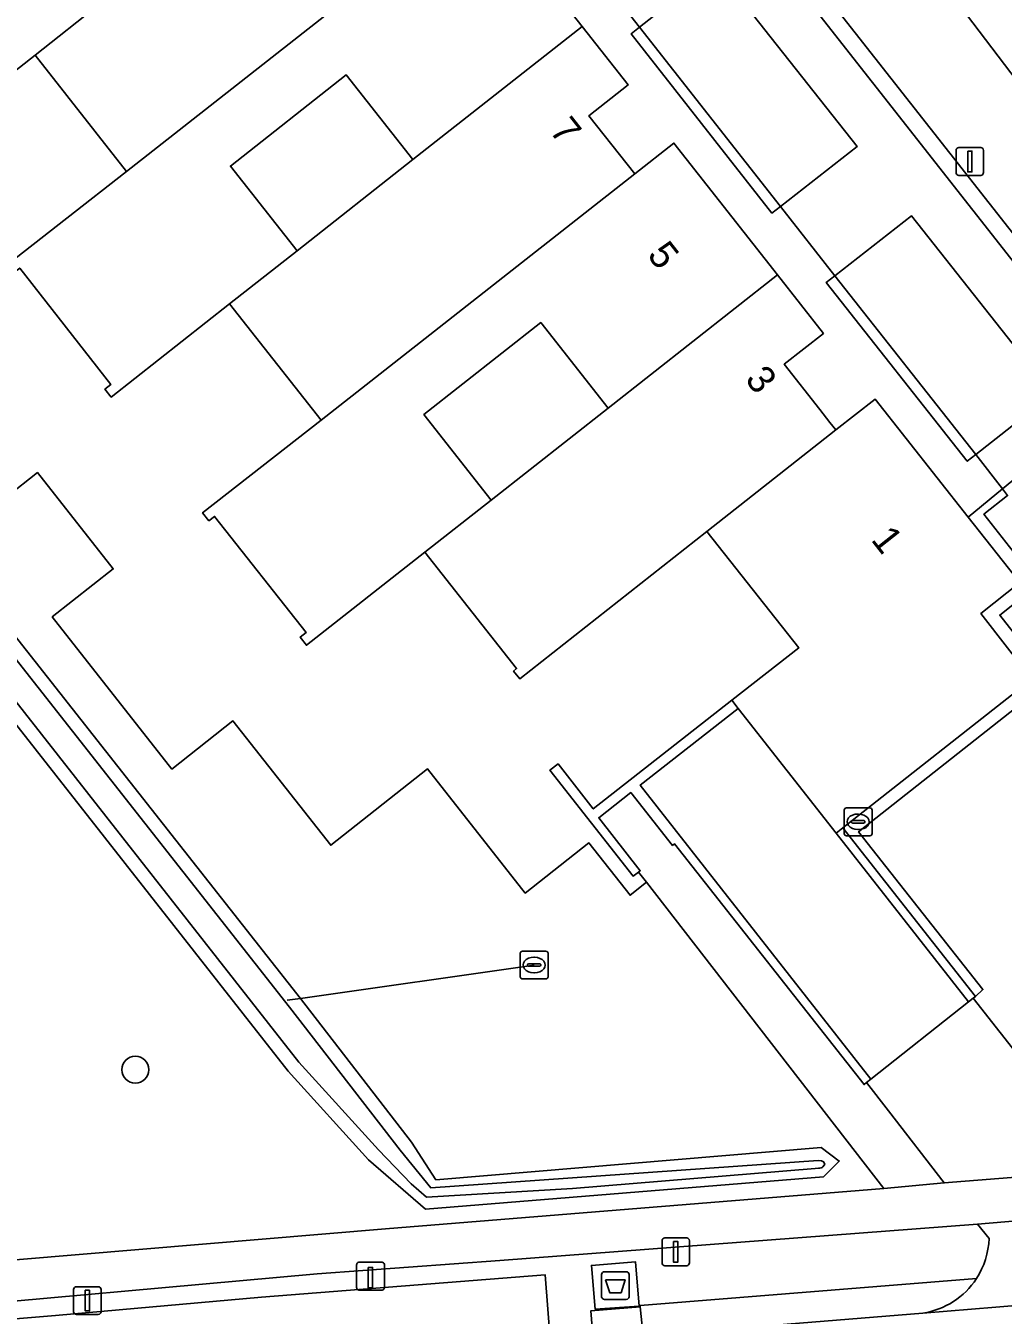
# Model space of a CAD drawing. Extents: x 156661 to 157576, y 383570 to 384425.
# Drawn here: x 157036.77 to 157072.04, y 383934.25 to 383980.76 of the extents above; entities that cross this region are included whole.
import ezdxf

# ---------------------------------------------------------------- set-up
doc = ezdxf.new("R2010")
doc.units = 0
for name, color, linetype in [('IMGEO_Afval_apart_plaats', 7, 'Continuous'), ('IMGEO_Berm_groen', 7, 'Continuous'), ('IMGEO_Boom', 7, 'Continuous'), ('IMGEO_Brandkraan', 7, 'Continuous'), ('IMGEO_Duiker', 7, 'Continuous'), ('IMGEO_Erf', 7, 'Continuous'), ('IMGEO_Fietspad_gesloten', 7, 'Continuous'), ('IMGEO_Groenvoorziening', 7, 'Continuous'), ('IMGEO_Laadpaal', 7, 'Continuous'), ('IMGEO_Lichtmast', 7, 'Continuous'), ('IMGEO_Muur', 7, 'Continuous'), ('IMGEO_Oever', 7, 'Continuous'), ('IMGEO_Pand', 7, 'Continuous'), ('IMGEO_Pand_nummerreeks', 7, 'Continuous'), ('IMGEO_Parkeervlak_open', 7, 'Continuous'), ('IMGEO_Rijbaan_lokaal_gesloten', 7, 'Continuous'), ('IMGEO_Rijbaan_lokaal_open', 7, 'Continuous'), ('IMGEO_Rioolput', 7, 'Continuous'), ('IMGEO_Voetpad_gesloten', 7, 'Continuous'), ('IMGEO_Voetpad_open', 7, 'Continuous'), ('IMGEO_Waterloop', 7, 'Continuous')]:
    doc.layers.add(name, color=color, linetype=linetype)

msp = doc.modelspace()

# ---------------------------------------------------------------- linework, layer by layer
at = {"layer": 'IMGEO_Afval_apart_plaats'}
for p, q in [((157057.55, 383934.917), (157057.55, 383935.717)), ((157057.55, 383935.717), (157057.55, 383934.917)), ((157057.65, 383935.817), (157058.44, 383935.817)), ((157058.44, 383935.817), (157057.65, 383935.817)), ((157058.54, 383935.717), (157058.54, 383934.917)), ((157058.54, 383934.917), (157058.54, 383935.717)), ((157058.44, 383934.817), (157057.65, 383934.817)), ((157057.65, 383934.817), (157058.44, 383934.817))]:
    msp.add_line(p, q, dxfattribs=at)
msp.add_lwpolyline([(157057.693, 383935.531), (157058.397, 383935.531), (157058.248, 383935.061), (157057.842, 383935.061), (157057.693, 383935.531)], dxfattribs=at)
for centre, start, end in [((157057.65, 383935.717), 90, 180), ((157057.65, 383935.717), 90, 180), ((157058.44, 383935.717), 0, 90), ((157058.44, 383935.717), 360, 90), ((157057.65, 383934.917), 180, 270), ((157057.65, 383934.917), 180, 270), ((157058.44, 383934.917), 270, 0), ((157058.44, 383934.917), 270, 0)]:
    msp.add_arc(centre, 0.1, start, end, dxfattribs=at)
at = {"layer": 'IMGEO_Berm_groen'}
for points in [[(157063.404, 383990.789), (157060.448, 383988.467), (157093.57, 383946.344), (157095.404, 383947.68)], [(157089.259, 383956.768), (157063.404, 383990.789)], [(157071.526, 383937.018), (157071.115, 383937.537), (157053.882, 383936.219), (157047.285, 383935.737), (157032.066, 383934.37), (156967.792, 383928.413), (156970.285, 383925.601), (156970.036, 383928.144), (156971.344, 383928.273), (156979.881, 383929.112), (156997.191, 383930.813), (157022.212, 383932.944), (157037.851, 383934.234), (157045.273, 383934.895), (157055.512, 383935.702), (157055.71, 383933.229), (157057.249, 383933.355), (157057.154, 383934.404), (157058.945, 383934.553), (157058.941, 383934.597), (157071.071, 383935.569)]]:
    msp.add_lwpolyline(points, dxfattribs=at)
msp.add_lwpolyline([(157058.904, 383934.58), (157057.318, 383934.466), (157057.183, 383936.043), (157058.771, 383936.176)], close=True, dxfattribs=at)
msp.add_arc((157068.713, 383937.106), 2.815, 326.9161, 358.2183, dxfattribs=at)
at = {"layer": 'IMGEO_Boom'}
msp.add_circle((157040.724, 383943.105), 0.489, dxfattribs=at)
at = {"layer": 'IMGEO_Brandkraan'}
for p, q in [((157066.304, 383951.619), (157066.304, 383952.471)), ((157066.379, 383952.545), (157067.231, 383952.545)), ((157066.792, 383952.325), (157066.817, 383952.325)), ((157067.305, 383952.471), (157067.305, 383951.619)), ((157066.563, 383952.039), (157066.563, 383952.051)), ((157067.001, 383952.002), (157066.603, 383952.002)), ((157066.606, 383952.088), (157067.004, 383952.088)), ((157067.047, 383952.051), (157067.047, 383952.039)), ((157067.231, 383951.545), (157066.379, 383951.545)), ((157066.815, 383951.765), (157066.79, 383951.765))]:
    msp.add_line(p, q, dxfattribs=at)
for points in [[(157066.304, 383951.619), (157066.304, 383952.471)], [(157066.379, 383952.545), (157067.231, 383952.545)], [(157067.305, 383952.471), (157067.305, 383951.619)], [(157067.231, 383951.545), (157066.379, 383951.545)]]:
    msp.add_lwpolyline(points, dxfattribs=at)
for centre, radius, start, end in [((157066.381, 383952.469), 0.0765, 91.552, 178.448), ((157066.381, 383952.469), 0.0765, 91.552, 178.448), ((157067.229, 383952.469), 0.0765, 1.552, 88.448), ((157067.229, 383952.469), 0.0765, 1.552, 88.448), ((157066.603, 383952.048), 0.0403, 85.8775, 175.7526), ((157066.6, 383952.038), 0.0366, 178.938, 274.7102), ((157067.004, 383952.045), 0.043, 264.8664, 352.4533), ((157067.008, 383952.05), 0.0386, 1.7309, 96.639), ((157066.381, 383951.621), 0.0765, 181.552, 268.448), ((157066.381, 383951.621), 0.0765, 181.552, 268.448), ((157067.229, 383951.621), 0.0765, 271.552, 358.448), ((157067.229, 383951.621), 0.0765, 271.552, 358.448)]:
    msp.add_arc(centre, radius, start, end, dxfattribs=at)
for centre, major_axis, ratio, start_param, end_param in [((157066.791, 383952.045), (-0.387, 0.002), 0.722429, 4.712389, 7.853982), ((157066.816, 383952.045), (-0.39, 0.002), 0.717154, 1.570796, 4.712389)]:
    msp.add_ellipse(centre, major_axis=major_axis, ratio=ratio, start_param=start_param, end_param=end_param, dxfattribs=at)
at = {"layer": 'IMGEO_Duiker'}
msp.add_lwpolyline([(157046.201, 383945.607), (157046.683, 383945.676), (157055.116, 383946.879)], dxfattribs=at)
at = {"layer": 'IMGEO_Erf'}
for points in [[(157053.11, 383985.486), (157056.845, 383980.735), (157058.505, 383978.625), (157057.09, 383977.512), (157058.743, 383975.415), (157060.159, 383976.527), (157063.891, 383971.776), (157065.55, 383969.664), (157064.135, 383968.552), (157065.422, 383966.915), (157065.787, 383966.451), (157065.999, 383966.182), (157067.413, 383967.295), (157070.773, 383963.032), (157072.009, 383964.052), (157071.046, 383965.29), (157070.739, 383965.049), (157065.654, 383971.5), (157065.96, 383971.742), (157064.001, 383974.244), (157063.694, 383974.003), (157058.612, 383980.465), (157058.919, 383980.706), (157056.954, 383983.211)], [(157036.106, 383972.141), (157040.402, 383975.505), (157037.106, 383979.7), (157032.805, 383976.321)], [(157034.995, 383962.908), (157037.195, 383964.64), (157039.929, 383961.167), (157037.729, 383959.435), (157042.046, 383953.95), (157044.246, 383955.682), (157047.773, 383951.203), (157051.268, 383953.956), (157054.795, 383949.476), (157057.089, 383951.283), (157058.574, 383949.397), (157059.17, 383949.866), (157058.881, 383950.231), (157058.684, 383950.086), (157055.684, 383953.903), (157055.975, 383954.132), (157057.249, 383952.511), (157062.248, 383956.428), (157064.661, 383958.319), (157061.345, 383962.52), (157054.596, 383957.207), (157054.37, 383957.482), (157054.482, 383957.573), (157051.171, 383961.766), (157046.901, 383958.415), (157046.673, 383958.706), (157046.885, 383958.873), (157043.583, 383963.061), (157043.378, 383962.902), (157043.151, 383963.194), (157047.431, 383966.531), (157044.124, 383970.724), (157039.859, 383967.365), (157039.63, 383967.648), (157039.84, 383967.818), (157036.555, 383972.018)]]:
    msp.add_lwpolyline(points, dxfattribs=at)
for points in [[(157046.559, 383972.64), (157050.739, 383975.93), (157048.336, 383978.984), (157044.156, 383975.694)], [(157053.565, 383963.65), (157057.781, 383966.968), (157055.353, 383970.054), (157051.137, 383966.736)]]:
    msp.add_lwpolyline(points, close=True, dxfattribs=at)
at = {"layer": 'IMGEO_Fietspad_gesloten'}
msp.add_lwpolyline([(156992.1, 384084.489), (156997.679, 384077.272), (157008.067, 384063.603), (157009.29, 384061.994), (157062.312, 383992.226), (157063.404, 383990.789), (157089.259, 383956.768)], dxfattribs=at)
at = {"layer": 'IMGEO_Groenvoorziening'}
for points in [[(157046.683, 383945.676), (157050.688, 383940.493), (157051.572, 383939.133), (157065.473, 383940.297), (157066.12, 383939.807), (157065.553, 383939.239), (157051.199, 383938.08), (157049.143, 383939.851), (157046.243, 383943.057), (156999.575, 384002.48), (156979.971, 384027.441), (156979.057, 384027.27), (156978.106, 384028.607), (156978.828, 384029.096), (156976.159, 384036.79), (156976.265, 384037.915)], [(156977.044, 384038.227), (156977.796, 384037.236), (156980.256, 384030.02), (157001.17, 384003.466), (157046.683, 383945.676)], [(157074.729, 383966.297), (157072.009, 383964.052), (157072.196, 383963.812), (157071.339, 383963.137), (157073.325, 383960.616), (157071.911, 383959.501), (157073.761, 383957.153), (157066.822, 383951.69), (157071.306, 383945.993), (157071.042, 383945.746), (157070.957, 383945.682), (157075.823, 383939.488), (157083.24, 383940.16)], [(157027.632, 383935.51), (157049.754, 383937.359), (157067.736, 383938.825), (157059.17, 383949.866), (157058.574, 383949.397), (157057.089, 383951.283), (157054.795, 383949.476), (157051.268, 383953.956), (157047.773, 383951.203), (157044.246, 383955.682), (157042.046, 383953.95), (157037.729, 383959.435), (157039.929, 383961.167), (157037.195, 383964.64), (157034.995, 383962.908)]]:
    msp.add_lwpolyline(points, dxfattribs=at)
for points in [[(157061.655, 383982.874), (157058.919, 383980.706), (157064.001, 383974.244), (157066.772, 383976.407)], [(157068.728, 383973.903), (157065.96, 383971.742), (157071.046, 383965.29), (157073.818, 383967.471)]]:
    msp.add_lwpolyline(points, close=True, dxfattribs=at)
at = {"layer": 'IMGEO_Laadpaal'}
for p, q in [((157048.711, 383936.074), (157048.711, 383935.233)), ((157048.711, 383936.074), (157048.711, 383935.233)), ((157049.627, 383936.158), (157048.786, 383936.158)), ((157049.627, 383936.158), (157048.786, 383936.158)), ((157049.711, 383935.242), (157049.711, 383936.083)), ((157049.711, 383935.242), (157049.711, 383936.083)), ((157048.795, 383935.158), (157049.636, 383935.158)), ((157048.795, 383935.158), (157049.636, 383935.158))]:
    msp.add_line(p, q, dxfattribs=at)
msp.add_lwpolyline([(157049.126, 383935.971), (157049.286, 383935.971), (157049.286, 383935.238), (157049.126, 383935.238), (157049.126, 383935.971)], dxfattribs=at)
for centre, start, end in [((157048.789, 383936.08), 92.4484, 184.2845), ((157048.789, 383936.08), 92.4484, 184.2845), ((157049.633, 383936.08), 2.4484, 94.2845), ((157049.633, 383936.08), 2.4484, 94.2845), ((157048.789, 383935.236), 182.4484, 274.2845), ((157048.789, 383935.236), 182.4484, 274.2845), ((157049.633, 383935.236), 272.4484, 4.2845), ((157049.633, 383935.236), 272.4484, 4.2845)]:
    msp.add_arc(centre, 0.0779, start, end, dxfattribs=at)
at = {"layer": 'IMGEO_Lichtmast'}
for p, q in [((157070.336, 383975.463), (157070.336, 383976.263)), ((157070.336, 383976.263), (157070.336, 383975.463)), ((157070.436, 383976.363), (157071.226, 383976.363)), ((157071.226, 383976.363), (157070.436, 383976.363)), ((157071.326, 383976.263), (157071.326, 383975.463)), ((157071.326, 383975.463), (157071.326, 383976.263)), ((157071.226, 383975.363), (157070.436, 383975.363)), ((157070.436, 383975.363), (157071.226, 383975.363)), ((157059.828, 383937.036), (157060.618, 383937.036)), ((157060.618, 383937.036), (157059.828, 383937.036)), ((157059.728, 383936.136), (157059.728, 383936.936)), ((157059.728, 383936.936), (157059.728, 383936.136)), ((157060.718, 383936.936), (157060.718, 383936.136)), ((157060.718, 383936.136), (157060.718, 383936.936)), ((157060.618, 383936.036), (157059.828, 383936.036)), ((157059.828, 383936.036), (157060.618, 383936.036)), ((157038.5, 383934.377), (157038.5, 383935.177)), ((157038.5, 383935.177), (157038.5, 383934.377)), ((157038.6, 383935.277), (157039.39, 383935.277)), ((157039.39, 383935.277), (157038.6, 383935.277)), ((157039.49, 383935.177), (157039.49, 383934.377)), ((157039.49, 383934.377), (157039.49, 383935.177)), ((157039.39, 383934.277), (157038.6, 383934.277)), ((157038.6, 383934.277), (157039.39, 383934.277))]:
    msp.add_line(p, q, dxfattribs=at)
for points in [[(157070.756, 383976.238), (157070.906, 383976.238), (157070.906, 383975.488), (157070.756, 383975.488), (157070.756, 383976.238)], [(157060.148, 383936.911), (157060.298, 383936.911), (157060.298, 383936.161), (157060.148, 383936.161), (157060.148, 383936.911)], [(157038.92, 383935.152), (157039.07, 383935.152), (157039.07, 383934.402), (157038.92, 383934.402), (157038.92, 383935.152)]]:
    msp.add_lwpolyline(points, dxfattribs=at)
for centre, start, end in [((157070.436, 383976.263), 90, 180), ((157070.436, 383976.263), 90, 180), ((157071.226, 383976.263), 0, 90), ((157071.226, 383976.263), 360, 90), ((157070.436, 383975.463), 180, 270), ((157070.436, 383975.463), 180, 270), ((157071.226, 383975.463), 270, 0), ((157071.226, 383975.463), 270, 0), ((157059.828, 383936.936), 90, 180), ((157059.828, 383936.936), 90, 180), ((157060.618, 383936.936), 0, 90), ((157060.618, 383936.936), 360, 90), ((157059.828, 383936.136), 180, 270), ((157059.828, 383936.136), 180, 270), ((157060.618, 383936.136), 270, 0), ((157060.618, 383936.136), 270, 0), ((157038.6, 383935.177), 90, 180), ((157038.6, 383935.177), 90, 180), ((157039.39, 383935.177), 0, 90), ((157039.39, 383935.177), 360, 90), ((157038.6, 383934.377), 180, 270), ((157038.6, 383934.377), 180, 270), ((157039.39, 383934.377), 270, 0), ((157039.39, 383934.377), 270, 0)]:
    msp.add_arc(centre, 0.1, start, end, dxfattribs=at)
at = {"layer": 'IMGEO_Muur'}
for points in [[(157058.919, 383980.706), (157058.612, 383980.465), (157063.694, 383974.003), (157064.001, 383974.244)], [(157065.96, 383971.742), (157065.654, 383971.5), (157070.739, 383965.049), (157071.046, 383965.29)], [(157071.042, 383945.746), (157071.306, 383945.993), (157066.822, 383951.69), (157073.761, 383957.153), (157071.911, 383959.501), (157073.325, 383960.616), (157071.339, 383963.137), (157072.196, 383963.812), (157072.009, 383964.052), (157070.773, 383963.032), (157072.633, 383960.672), (157071.232, 383959.559), (157073.067, 383957.196), (157066.256, 383951.828)], [(157057.249, 383952.511), (157055.975, 383954.132), (157055.684, 383953.903), (157058.684, 383950.086), (157058.881, 383950.231), (157058.942, 383950.278), (157057.444, 383952.194), (157058.602, 383953.1), (157060.106, 383951.194), (157060.178, 383951.252), (157067.017, 383942.57), (157067.104, 383942.64), (157067.264, 383942.768), (157058.943, 383953.37), (157062.475, 383956.138), (157062.248, 383956.428)], [(157071.042, 383945.746), (157066.256, 383951.828), (157066.015, 383951.639), (157070.785, 383945.551), (157070.957, 383945.682)]]:
    msp.add_lwpolyline(points, close=True, dxfattribs=at)
at = {"layer": 'IMGEO_Oever'}
for points in [[(156976.265, 384037.915), (156976.159, 384036.79), (156978.828, 384029.096), (156978.106, 384028.607), (156979.057, 384027.27), (156979.971, 384027.441), (156999.575, 384002.48), (157046.243, 383943.057), (157049.143, 383939.851), (157051.199, 383938.08), (157065.553, 383939.239), (157066.12, 383939.807), (157065.473, 383940.297), (157051.572, 383939.133), (157050.688, 383940.493), (157046.683, 383945.676), (157001.17, 384003.466), (156980.256, 384030.02)], [(157029.374, 383966.839), (157046.286, 383945.366), (157050.277, 383940.201), (157051.383, 383938.849), (157065.364, 383939.825), (157065.479, 383939.817), (157065.509, 383939.807), (157065.555, 383939.782), (157065.595, 383939.726), (157065.597, 383939.703), (157065.582, 383939.657), (157065.534, 383939.6), (157065.511, 383939.583), (157065.468, 383939.563), (157065.421, 383939.553), (157065.372, 383939.55), (157065.257, 383939.543), (157056.494, 383938.823), (157051.23, 383938.505), (157050.675, 383938.988), (157049.496, 383940.212), (157046.629, 383943.382), (157028.661, 383966.26)]]:
    msp.add_lwpolyline(points, dxfattribs=at)
at = {"layer": 'IMGEO_Pand'}
for points in [[(157043.672, 383984.868), (157049.803, 383989.693), (157046.041, 383994.477), (157044.634, 383993.37), (157033.325, 383984.498), (157029.036, 383981.139), (157029.261, 383980.846), (157029.468, 383981.005), (157032.788, 383976.809), (157032.568, 383976.652), (157032.805, 383976.321), (157037.106, 383979.7), (157039.483, 383981.571), (157037.01, 383984.714), (157041.198, 383988.011)], [(157051.695, 383984.374), (157050.049, 383986.469), (157051.464, 383987.581), (157049.803, 383989.693), (157043.672, 383984.868), (157039.483, 383981.571), (157037.106, 383979.7), (157040.402, 383975.505)], [(157050.739, 383975.93), (157056.845, 383980.735), (157053.11, 383985.486), (157051.695, 383984.374), (157040.402, 383975.505), (157036.106, 383972.141), (157036.331, 383971.847), (157036.555, 383972.018), (157039.84, 383967.818), (157039.63, 383967.648), (157039.859, 383967.365), (157044.124, 383970.724), (157046.559, 383972.64), (157044.156, 383975.694), (157048.336, 383978.984)], [(157058.743, 383975.415), (157057.09, 383977.512), (157058.505, 383978.625), (157056.845, 383980.735), (157050.739, 383975.93), (157046.559, 383972.64), (157044.124, 383970.724), (157047.431, 383966.531)], [(157057.781, 383966.968), (157063.891, 383971.776), (157060.159, 383976.527), (157058.743, 383975.415), (157047.431, 383966.531), (157043.151, 383963.194), (157043.378, 383962.902), (157043.583, 383963.061), (157046.885, 383958.873), (157046.673, 383958.706), (157046.901, 383958.415), (157051.171, 383961.766), (157053.565, 383963.65), (157051.137, 383966.736), (157055.353, 383970.054)], [(157065.999, 383966.182), (157065.787, 383966.451), (157065.422, 383966.915), (157064.135, 383968.552), (157065.55, 383969.664), (157063.891, 383971.776), (157057.781, 383966.968), (157053.565, 383963.65), (157051.171, 383961.766), (157054.482, 383957.573), (157054.37, 383957.482), (157054.596, 383957.207), (157061.345, 383962.52)], [(157071.232, 383959.559), (157072.633, 383960.672), (157070.773, 383963.032), (157067.413, 383967.295), (157065.999, 383966.182), (157061.345, 383962.52), (157064.661, 383958.319), (157062.248, 383956.428), (157062.475, 383956.138), (157066.015, 383951.639), (157066.256, 383951.828), (157073.067, 383957.196)]]:
    msp.add_lwpolyline(points, close=True, dxfattribs=at)
at = {"layer": 'IMGEO_Parkeervlak_open'}
msp.add_lwpolyline([(157055.71, 383933.229), (157055.512, 383935.702), (157045.273, 383934.895), (157037.851, 383934.234), (157022.212, 383932.944), (156997.191, 383930.813), (156979.881, 383929.112), (156971.344, 383928.273), (156970.036, 383928.144), (156970.285, 383925.601), (156970.506, 383925.623), (157009.562, 383929.446)], close=True, dxfattribs=at)
at = {"layer": 'IMGEO_Rijbaan_lokaal_gesloten'}
msp.add_lwpolyline([(157066.015, 383951.639), (157062.475, 383956.138), (157058.943, 383953.37), (157067.264, 383942.768), (157070.785, 383945.551)], close=True, dxfattribs=at)
at = {"layer": 'IMGEO_Rijbaan_lokaal_open'}
msp.add_lwpolyline([(157070.957, 383945.682), (157070.785, 383945.551), (157067.264, 383942.768), (157067.104, 383942.64), (157067.897, 383941.617), (157069.913, 383939.019), (157075.823, 383939.488)], close=True, dxfattribs=at)
for points in [[(157077.95, 383936.786), (157077.04, 383938.041), (157071.115, 383937.537), (157071.526, 383937.018)], [(157025.823, 383926.256), (157051.661, 383928.368), (157069.999, 383929.742), (157075.258, 383930.194), (157101.55, 383932.451), (157099.825, 383936.843), (157080.659, 383935.273), (157071.766, 383934.544), (157069.139, 383934.324), (157059.045, 383933.502), (157057.249, 383933.355), (157055.71, 383933.229), (157009.562, 383929.446)], [(157071.071, 383935.569), (157058.941, 383934.597), (157058.945, 383934.553), (157059.045, 383933.502), (157069.139, 383934.324)], [(157069.139, 383934.324), (157071.766, 383934.544), (157080.659, 383935.273)]]:
    msp.add_lwpolyline(points, dxfattribs=at)
for centre, radius, start, end in [((157068.713, 383937.106), 2.815, 326.9161, 358.2183), ((157068.719, 383937.098), 2.805, 278.6153, 326.981), ((157068.719, 383937.098), 2.805, 278.6153, 326.981)]:
    msp.add_arc(centre, radius, start, end, dxfattribs=at)
at = {"layer": 'IMGEO_Rioolput'}
for p, q in [((157054.615, 383946.453), (157054.615, 383947.305)), ((157054.69, 383947.379), (157055.542, 383947.379)), ((157055.616, 383947.305), (157055.616, 383946.453)), ((157054.874, 383946.873), (157054.874, 383946.885)), ((157055.312, 383946.836), (157054.914, 383946.836)), ((157054.917, 383946.922), (157055.315, 383946.922)), ((157055.103, 383947.159), (157055.128, 383947.159)), ((157055.358, 383946.885), (157055.358, 383946.873)), ((157055.542, 383946.379), (157054.69, 383946.379)), ((157055.126, 383946.599), (157055.101, 383946.599))]:
    msp.add_line(p, q, dxfattribs=at)
for points in [[(157054.615, 383946.453), (157054.615, 383947.305)], [(157054.69, 383947.379), (157055.542, 383947.379)], [(157055.616, 383947.305), (157055.616, 383946.453)], [(157055.542, 383946.379), (157054.69, 383946.379)]]:
    msp.add_lwpolyline(points, dxfattribs=at)
for centre, radius, start, end in [((157054.692, 383947.303), 0.0765, 91.552, 178.448), ((157054.692, 383947.303), 0.0765, 91.552, 178.448), ((157055.54, 383947.303), 0.0765, 1.552, 88.448), ((157055.54, 383947.303), 0.0765, 1.552, 88.448), ((157054.914, 383946.882), 0.0403, 85.8775, 175.7526), ((157054.911, 383946.872), 0.0366, 178.938, 274.7102), ((157055.315, 383946.879), 0.043, 264.8664, 352.4533), ((157055.319, 383946.884), 0.0386, 1.7309, 96.639), ((157054.692, 383946.455), 0.0765, 181.552, 268.448), ((157054.692, 383946.455), 0.0765, 181.552, 268.448), ((157055.54, 383946.455), 0.0765, 271.552, 358.448), ((157055.54, 383946.455), 0.0765, 271.552, 358.448)]:
    msp.add_arc(centre, radius, start, end, dxfattribs=at)
for centre, major_axis, ratio, start_param, end_param in [((157055.102, 383946.879), (-0.387, 0.002), 0.722429, 4.712389, 7.853982), ((157055.127, 383946.879), (-0.39, 0.002), 0.717154, 1.570796, 4.712389)]:
    msp.add_ellipse(centre, major_axis=major_axis, ratio=ratio, start_param=start_param, end_param=end_param, dxfattribs=at)
at = {"layer": 'IMGEO_Voetpad_gesloten'}
msp.add_lwpolyline([(157040.516, 384009.769), (157045.574, 384003.367), (157042.841, 384001.163), (157044.807, 383998.655), (157047.556, 384000.837), (157052.649, 383994.382), (157049.887, 383992.202), (157051.887, 383989.668), (157054.649, 383991.843), (157059.636, 383985.337), (157056.954, 383983.211), (157058.919, 383980.706), (157061.655, 383982.874), (157066.772, 383976.407), (157064.001, 383974.244), (157065.96, 383971.742), (157068.728, 383973.903), (157073.818, 383967.471), (157071.046, 383965.29), (157072.009, 383964.052), (157074.729, 383966.297), (157091.566, 383944.874), (157093.064, 383945.973), (157004.709, 384058.354)], dxfattribs=at)
msp.add_lwpolyline([(157058.771, 383936.176), (157057.183, 383936.043), (157057.318, 383934.466), (157058.904, 383934.58)], close=True, dxfattribs=at)
at = {"layer": 'IMGEO_Voetpad_open'}
for points in [[(157059.34, 383989.875), (157005.166, 384058.77), (157004.709, 384058.354), (157093.064, 383945.973), (157093.57, 383946.344), (157060.448, 383988.467)], [(157060.178, 383951.252), (157060.106, 383951.194), (157058.602, 383953.1), (157057.444, 383952.194), (157058.942, 383950.278), (157058.881, 383950.231), (157059.17, 383949.866), (157067.736, 383938.825), (157069.913, 383939.019), (157067.897, 383941.617), (157067.104, 383942.64), (157067.017, 383942.57)], [(157058.945, 383934.553), (157057.154, 383934.404), (157057.249, 383933.355), (157059.045, 383933.502)]]:
    msp.add_lwpolyline(points, close=True, dxfattribs=at)
for points in [[(157083.24, 383940.16), (157075.823, 383939.488), (157069.913, 383939.019), (157067.736, 383938.825), (157049.754, 383937.359), (157027.632, 383935.51), (157012.523, 383934.255), (157008.85, 383933.899), (156966.535, 383929.792), (156967.792, 383928.413), (157032.066, 383934.37), (157047.285, 383935.737)], [(157047.285, 383935.737), (157053.882, 383936.219), (157071.115, 383937.537), (157077.04, 383938.041), (157084.268, 383938.674)]]:
    msp.add_lwpolyline(points, dxfattribs=at)
at = {"layer": 'IMGEO_Waterloop'}
msp.add_lwpolyline([(157028.661, 383966.26), (157046.629, 383943.382), (157049.496, 383940.212), (157050.675, 383938.988), (157051.23, 383938.505), (157056.494, 383938.823), (157065.257, 383939.543), (157065.372, 383939.55), (157065.421, 383939.553), (157065.468, 383939.563), (157065.511, 383939.583), (157065.534, 383939.6), (157065.582, 383939.657), (157065.597, 383939.703), (157065.595, 383939.726), (157065.555, 383939.782), (157065.509, 383939.807), (157065.479, 383939.817), (157065.364, 383939.825), (157051.383, 383938.849), (157050.277, 383940.201), (157046.286, 383945.366), (157029.374, 383966.839)], dxfattribs=at)

# ---------------------------------------------------------------- texts
at = {"layer": 'IMGEO_Pand_nummerreeks'}
for s, rotation, p in [('7', 308.1817, (157055.639, 383976.962)), ('5', 308.1817, (157059.165, 383972.477)), ('3', 308.1817, (157062.691, 383967.993)), ('1', 308.239, (157067.24, 383962.215))]:
    msp.add_text(s, height=1, rotation=rotation, dxfattribs=at).set_placement(p)

doc.saveas('drawing.dxf')
